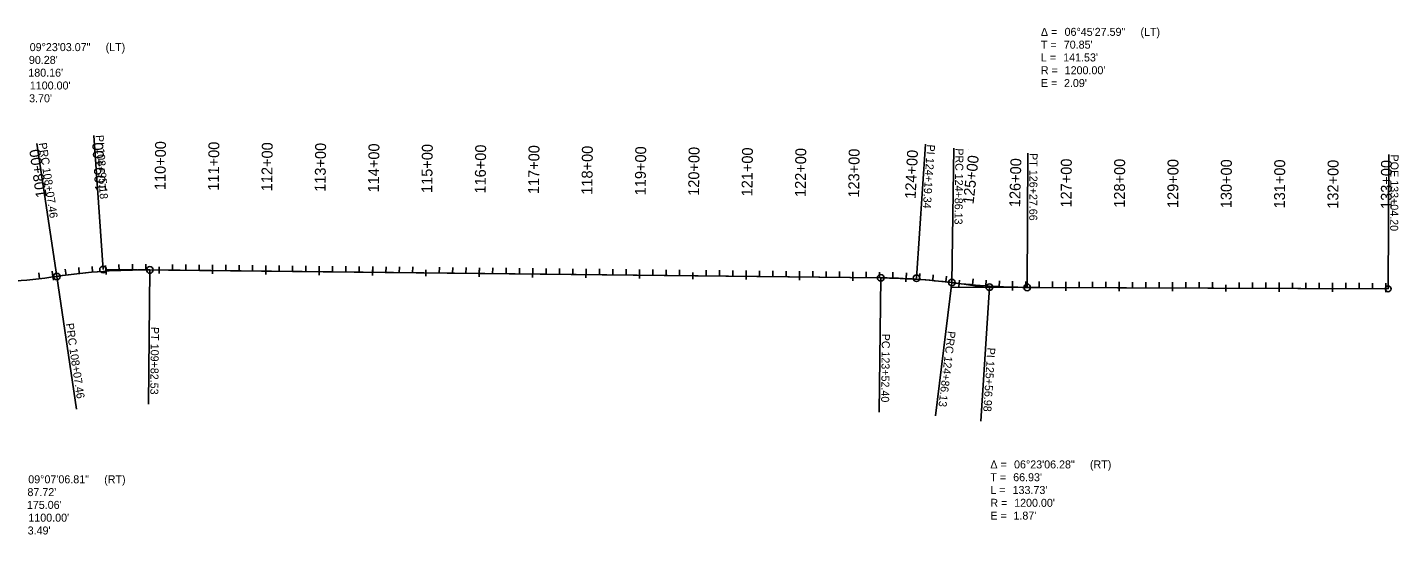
# Model space of a CAD drawing. Extents: x 20504372 to 20508399, y 7970077 to 7971028.
# Drawn here: x 20505829 to 20508399, y 7970077 to 7971028 of the extents above; entities that cross this region are included whole.
import ezdxf

# ---------------------------------------------------------------- set-up
doc = ezdxf.new("R2010")
doc.units = 0
for name, color, linetype in [('SurAlignment', 7, 'Continuous'), ('SurMiscNotes', 7, 'Continuous'), ('TextAlignment', 7, 'Continuous'), ('TextAlignmentSml', 7, 'Continuous')]:
    doc.layers.add(name, color=color, linetype=linetype)

msp = doc.modelspace()

# ---------------------------------------------------------------- linework, layer by layer
at = {"layer": 'SurAlignment'}
for p, q in [((20505977.2, 7970574.1), (20507428.1, 7970558.5)), ((20506058.3, 7970573.3), (20507428.1, 7970558.5)), ((20506058.3, 7970573.3), (20507428.1, 7970558.5)), ((20506058.3, 7970573.3), (20506058.3, 7970573.3)), ((20506058.3, 7970573.3), (20507428.1, 7970558.5)), ((20507562.2, 7970541.2), (20508379.2, 7970537.7)), ((20507702.7, 7970540.6), (20508379.2, 7970537.7))]:
    msp.add_line(p, q, dxfattribs=at)
for centre, radius, start, end in [((20506046.5, 7969473.3), 1100, 89.3818, 98.534), ((20506046.5, 7969473.3), 1100, 89.3818, 98.5003), ((20506046.5, 7969473.3), 1100, 89.3818, 98.5003), ((20505721.3, 7971649.2), 1100, 269.1162, 278.5003), ((20505721.3, 7971649.2), 1100, 269.1162, 278.5003), ((20507415.2, 7969358.5), 1200, 80.1492, 89.3818), ((20507415.2, 7969358.5), 1200, 82.9967, 89.3818), ((20507415.2, 7969358.5), 1200, 82.9967, 89.3818), ((20507707.8, 7971740.6), 1200, 262.9967, 269.7544), ((20507707.8, 7971740.6), 1200, 262.9967, 269.7544)]:
    msp.add_arc(centre, radius, start, end, dxfattribs=at)
at = {"layer": 'SurMiscNotes'}
for p, q in [((20505876.5, 7970560.2), (20505874.9, 7970571)), ((20505975.9, 7970571), (20505975.2, 7970581.9)), ((20506075.9, 7970579.2), (20506075.7, 7970566.9)), ((20506175.8, 7970572), (20506175.9, 7970582.9)), ((20506275.8, 7970570.9), (20506275.9, 7970581.8)), ((20506375.8, 7970569.8), (20506375.9, 7970580.7)), ((20506475.8, 7970568.7), (20506475.9, 7970579.7)), ((20506575.8, 7970573.8), (20506575.7, 7970561.6)), ((20506675.8, 7970566.6), (20506675.9, 7970577.5)), ((20506775.8, 7970565.5), (20506775.9, 7970576.4)), ((20506875.8, 7970564.4), (20506875.9, 7970575.4)), ((20506975.8, 7970563.4), (20506975.9, 7970574.3)), ((20507075.8, 7970568.4), (20507075.7, 7970556.2)), ((20507175.7, 7970561.2), (20507175.9, 7970572.1)), ((20507275.7, 7970560.1), (20507275.9, 7970571)), ((20507375.7, 7970559), (20507375.9, 7970570)), ((20507475.7, 7970557), (20507476.3, 7970567.9)), ((20507576, 7970554.1), (20507574.6, 7970541.9)), ((20507675, 7970541.1), (20507675.3, 7970552)), ((20507775, 7970540.3), (20507775.1, 7970551.3)), ((20507875, 7970539.9), (20507875, 7970550.8)), ((20507975, 7970539.5), (20507975, 7970550.4)), ((20508075, 7970545.2), (20508075, 7970532.9)), ((20508175, 7970538.6), (20508175, 7970549.5)), ((20508275, 7970538.2), (20508275, 7970549.1)), ((20508375, 7970537.8), (20508375, 7970548.7))]:
    msp.add_line(p, q, dxfattribs=at)
at = {"layer": 'TextAlignment'}
for p, q in [((20505970.6, 7970574.2), (20505953.3, 7970825.6)), ((20505953.3, 7970825.6), (20505953.3, 7970825.6)), ((20505883.9, 7970561.2), (20505846.6, 7970810.5)), ((20505846.6, 7970810.5), (20505846.6, 7970810.5)), ((20507495.1, 7970557.8), (20507511.8, 7970809.2)), ((20507511.8, 7970809.2), (20507511.8, 7970809.2)), ((20507561.5, 7970549.6), (20507565, 7970801.6)), ((20507592.2, 7970799.7), (20507592.2, 7970799.7)), ((20507702.7, 7970540.6), (20507703.7, 7970792.6)), ((20507703.7, 7970792.6), (20507703.7, 7970792.6)), ((20508379.2, 7970537.7), (20508380.3, 7970789.7)), ((20508380.3, 7970789.7), (20508380.3, 7970789.7)), ((20506058.3, 7970573.3), (20506055.6, 7970321.3)), ((20505883.9, 7970561.2), (20505921.1, 7970312)), ((20507428.1, 7970558.5), (20507425.4, 7970306.5)), ((20507561.5, 7970549.6), (20507530.8, 7970299.5)), ((20507631.8, 7970541), (20507615.9, 7970289.5)), ((20505921.1, 7970312), (20505921.1, 7970312)), ((20506055.6, 7970321.3), (20506055.6, 7970321.3)), ((20507425.4, 7970306.5), (20507425.4, 7970306.5)), ((20507530.8, 7970299.5), (20507530.8, 7970299.5)), ((20507615.9, 7970289.5), (20507615.9, 7970289.5))]:
    msp.add_line(p, q, dxfattribs=at)
for centre, radius in [((20505883.9, 7970561.2), 6.24), ((20505883.9, 7970561.2), 6.24), ((20505970.6, 7970574.2), 6.24), ((20506058.3, 7970573.3), 6.24), ((20507428.1, 7970558.5), 6.24), ((20507495.1, 7970557.8), 6.24), ((20507561.5, 7970549.6), 6.24), ((20507561.5, 7970549.6), 6.24), ((20507631.8, 7970541), 6.24), ((20507702.7, 7970540.6), 6.24), ((20508379.2, 7970537.7), 5.34)]:
    msp.add_circle(centre, radius, dxfattribs=at)
at = {"layer": 'TextAlignmentSml'}
for p, q in [((20505851.7, 7970556.9), (20505850.4, 7970567.8)), ((20505875.6, 7970566.2), (20505877.4, 7970554.1)), ((20505901.2, 7970563.7), (20505899.8, 7970574.5)), ((20505926.1, 7970566.7), (20505924.9, 7970577.6)), ((20505950.9, 7970569.2), (20505950, 7970580)), ((20505975.5, 7970577.2), (20505976.3, 7970564.9)), ((20506000.8, 7970572.4), (20506000.4, 7970583.3)), ((20506025.8, 7970573.1), (20506025.6, 7970584)), ((20506050.8, 7970573.3), (20506050.9, 7970584.2)), ((20506075.9, 7970579.2), (20506075.7, 7970566.9)), ((20506100.8, 7970572.8), (20506100.9, 7970583.7)), ((20506125.8, 7970572.5), (20506125.9, 7970583.4)), ((20506150.8, 7970572.3), (20506150.9, 7970583.2)), ((20506175.9, 7970578.1), (20506175.7, 7970565.9)), ((20506200.8, 7970571.7), (20506200.9, 7970582.6)), ((20506225.8, 7970571.4), (20506225.9, 7970582.4)), ((20506250.8, 7970571.2), (20506250.9, 7970582.1)), ((20506275.9, 7970577), (20506275.7, 7970564.8)), ((20506300.8, 7970570.6), (20506300.9, 7970581.6)), ((20506325.8, 7970570.4), (20506325.9, 7970581.3)), ((20506350.8, 7970570.1), (20506350.9, 7970581)), ((20506375.9, 7970575.9), (20506375.7, 7970563.7)), ((20506400.8, 7970569.6), (20506400.9, 7970580.5)), ((20506425.8, 7970569.3), (20506425.9, 7970580.2)), ((20506450.8, 7970569), (20506450.9, 7970579.9)), ((20506475.9, 7970574.9), (20506475.7, 7970562.6)), ((20506500.8, 7970568.5), (20506500.9, 7970579.4)), ((20506525.8, 7970568.2), (20506525.9, 7970579.1)), ((20506550.8, 7970567.9), (20506550.9, 7970578.9)), ((20506575.8, 7970573.8), (20506575.7, 7970561.6)), ((20506600.8, 7970567.4), (20506600.9, 7970578.3)), ((20506625.8, 7970567.1), (20506625.9, 7970578.1)), ((20506650.8, 7970566.9), (20506650.9, 7970577.8)), ((20506675.8, 7970572.7), (20506675.7, 7970560.5)), ((20506700.8, 7970566.3), (20506700.9, 7970577.2)), ((20506725.8, 7970566.1), (20506725.9, 7970577)), ((20506750.8, 7970565.8), (20506750.9, 7970576.7)), ((20506775.8, 7970571.6), (20506775.7, 7970559.4)), ((20506800.8, 7970565.2), (20506800.9, 7970576.2)), ((20506825.8, 7970565), (20506825.9, 7970575.9)), ((20506850.8, 7970564.7), (20506850.9, 7970575.6)), ((20506875.8, 7970570.6), (20506875.7, 7970558.3)), ((20506900.8, 7970564.2), (20506900.9, 7970575.1)), ((20506925.8, 7970563.9), (20506925.9, 7970574.8)), ((20506950.8, 7970563.6), (20506950.9, 7970574.5)), ((20506975.8, 7970569.5), (20506975.7, 7970557.2)), ((20507000.8, 7970563.1), (20507000.9, 7970574)), ((20507025.8, 7970562.8), (20507025.9, 7970573.7)), ((20507050.8, 7970562.5), (20507050.9, 7970573.5)), ((20507075.8, 7970568.4), (20507075.7, 7970556.2)), ((20507100.8, 7970562), (20507100.9, 7970572.9)), ((20507125.8, 7970561.7), (20507125.9, 7970572.7)), ((20507150.7, 7970561.5), (20507150.9, 7970572.4)), ((20507175.8, 7970567.3), (20507175.7, 7970555.1)), ((20507200.7, 7970560.9), (20507200.9, 7970571.8)), ((20507225.7, 7970560.7), (20507225.9, 7970571.6)), ((20507250.7, 7970560.4), (20507250.9, 7970571.3)), ((20507275.8, 7970566.2), (20507275.7, 7970554)), ((20507300.7, 7970559.8), (20507300.9, 7970570.8)), ((20507325.7, 7970559.6), (20507325.9, 7970570.5)), ((20507350.7, 7970559.3), (20507350.9, 7970570.2)), ((20507375.8, 7970565.2), (20507375.7, 7970552.9)), ((20507400.7, 7970558.8), (20507400.9, 7970569.7)), ((20507425.7, 7970558.5), (20507425.9, 7970569.4)), ((20507450.7, 7970558), (20507451.1, 7970568.9)), ((20507500.7, 7970555.5), (20507501.4, 7970566.4)), ((20507525.6, 7970553.5), (20507526.6, 7970564.3)), ((20507476, 7970563.1), (20507475.4, 7970550.9)), ((20507550.4, 7970550.9), (20507551.7, 7970561.7)), ((20507576, 7970554.1), (20507574.6, 7970541.9)), ((20507600.1, 7970545.5), (20507601.1, 7970556.4)), ((20507625.1, 7970543.5), (20507625.8, 7970554.4)), ((20507650, 7970542), (20507650.6, 7970552.9)), ((20507675.2, 7970547.2), (20507674.8, 7970535)), ((20507700, 7970540.7), (20507700.1, 7970551.6)), ((20507725, 7970540.6), (20507725.1, 7970551.5)), ((20507750, 7970540.4), (20507750.1, 7970551.4)), ((20507775, 7970546.5), (20507775, 7970534.2)), ((20507800, 7970540.2), (20507800.1, 7970551.2)), ((20507825, 7970540.1), (20507825, 7970551)), ((20507850, 7970540), (20507850, 7970550.9)), ((20507875, 7970546), (20507875, 7970533.8)), ((20507900, 7970539.8), (20507900, 7970550.7)), ((20507925, 7970539.7), (20507925, 7970550.6)), ((20507950, 7970539.6), (20507950, 7970550.5)), ((20507975, 7970545.6), (20507975, 7970533.4)), ((20508000, 7970539.4), (20508000, 7970550.3)), ((20508025, 7970539.3), (20508025, 7970550.2)), ((20508050, 7970539.2), (20508050, 7970550.1)), ((20508075, 7970545.2), (20508075, 7970532.9)), ((20508100, 7970538.9), (20508100, 7970549.9)), ((20508125, 7970538.8), (20508125, 7970549.8)), ((20508150, 7970538.7), (20508150, 7970549.7)), ((20508175, 7970544.7), (20508175, 7970532.5)), ((20508200, 7970538.5), (20508200, 7970549.4)), ((20508225, 7970538.4), (20508225, 7970549.3)), ((20508250, 7970538.3), (20508250, 7970549.2)), ((20508275, 7970544.3), (20508275, 7970532.1)), ((20508300, 7970538.1), (20508300, 7970549)), ((20508325, 7970538), (20508325, 7970548.9)), ((20508350, 7970537.9), (20508350, 7970548.8)), ((20508375, 7970543.9), (20508375, 7970531.6))]:
    msp.add_line(p, q, dxfattribs=at)

# ---------------------------------------------------------------- texts
at = {"layer": 'SurMiscNotes'}
for s, rotation, p in [('110+00', 89.3818, (20506087.6, 7970722.9)), ('115+00', 89.3818, (20506587.6, 7970717.6)), ('120+00', 89.3818, (20507087.6, 7970712.2)), ('125+00', 83.6589, (20507602, 7970695.9)), ('130+00', 89.7544, (20508085.8, 7970689))]:
    msp.add_text(s, height=20.4, rotation=rotation, dxfattribs=at).set_placement(p)
at = {"layer": 'TextAlignment'}
for s, p in [('Δ = ', (20507728.3, 7971012.3)), ('06°45\'27.59"', (20507772.7, 7971012.3)), (' (LT)', (20507909.4, 7971012.3)), ('T = ', (20507728.3, 7970988.3)), ("70.85'", (20507771.2, 7970988.3)), ('09°23\'03.07"', (20505833.1, 7970983.7)), (' (LT)', (20505969.8, 7970983.7)), ('L = ', (20507728.3, 7970964.3)), ("141.53'", (20507770.1, 7970964.3)), ("180.16'", (20505830.5, 7970935.7)), ("90.28'", (20505831.6, 7970959.7)), ('R = ', (20507728.3, 7970940.3)), ("1200.00'", (20507772.9, 7970940.3)), ("1100.00'", (20505833.3, 7970911.7)), ('E = ', (20507728.3, 7970916.3)), ("2.09'", (20507771.6, 7970916.3)), ("3.70'", (20505832, 7970887.7)), ('Δ = ', (20507633.6, 7970201.1)), ('06°23\'06.28"', (20507678, 7970201.1)), (' (RT)', (20507814.7, 7970201.1)), ('09°07\'06.81"', (20505830.4, 7970173.2)), (' (RT)', (20505967.1, 7970173.2)), ('T = ', (20507633.6, 7970177.1)), ("66.93'", (20507676.4, 7970177.1)), ("87.72'", (20505828.9, 7970149.2)), ('L = ', (20507633.6, 7970153.1)), ("133.73'", (20507675.3, 7970153.1)), ("175.06'", (20505827.8, 7970125.2)), ('R = ', (20507633.6, 7970129.1)), ("1200.00'", (20507678.2, 7970129.1)), ("1100.00'", (20505830.6, 7970101.2)), ('E = ', (20507633.6, 7970105.1)), ("1.87'", (20507676.9, 7970105.1)), ("3.49'", (20505829.3, 7970077.2))]:
    msp.add_text(s, height=15, dxfattribs=at).set_placement(p)
for s, rotation, p in [('PI ', 273.9411, (20505956.6, 7970825.8)), ('PRC', 278.5003, (20505849.9, 7970811)), ('108+95.18', 273.9411, (20505958.3, 7970800.9)), ('PI ', 266.1892, (20507515.1, 7970809)), ('PRC', 269.2115, (20507568.3, 7970801.5)), ('124+19.34', 266.1892, (20507513.4, 7970784)), ('PT', 269.7544, (20507707, 7970792.6)), ('POE ', 269.7544, (20508383.6, 7970789.7)), ('108+07.46', 278.5003, (20505856.9, 7970763.9)), ('124+86.13', 269.2115, (20507567.6, 7970753.9)), ('126+27.66', 269.7544, (20507706.9, 7970761.1)), ('133+04.20', 269.7544, (20508383.4, 7970741.6)), ('PRC', 278.5003, (20505900.5, 7970472.5)), ('PT', 269.3818, (20506060.5, 7970466.5)), ('PC', 269.3818, (20507430.3, 7970453.8)), ('PRC', 262.9967, (20507553.7, 7970459.3)), ('108+07.46', 278.5003, (20505907.5, 7970425.4)), ('109+82.53', 269.3818, (20506060.1, 7970435)), ('123+52.40', 269.3818, (20507429.9, 7970420.5)), ('124+86.13', 262.9967, (20507547.9, 7970412)), ('PI ', 266.3755, (20507628, 7970428)), ('125+56.98', 266.3755, (20507626.4, 7970403.1))]:
    msp.add_text(s, height=15, rotation=rotation, dxfattribs=at).set_placement(p)
at = {"layer": 'TextAlignmentSml'}
for s, rotation, p in [('108+00', 98.1116, (20505865.4, 7970710.1)), ('109+00', 93.6804, (20505976.4, 7970721.4)), ('110+00', 89.3818, (20506087.6, 7970722.9)), ('111+00', 89.3818, (20506187.6, 7970721.9)), ('112+00', 89.3818, (20506287.6, 7970720.8)), ('113+00', 89.3818, (20506387.6, 7970719.7)), ('114+00', 89.3818, (20506487.6, 7970718.6)), ('115+00', 89.3818, (20506587.6, 7970717.6)), ('116+00', 89.3818, (20506687.6, 7970716.5)), ('117+00', 89.3818, (20506787.6, 7970715.4)), ('118+00', 89.3818, (20506887.6, 7970714.3)), ('119+00', 89.3818, (20506987.6, 7970713.2)), ('120+00', 89.3818, (20507087.6, 7970712.2)), ('121+00', 89.3818, (20507187.6, 7970711.1)), ('122+00', 89.3818, (20507287.6, 7970710)), ('123+00', 89.3818, (20507387.6, 7970708.9)), ('124+00', 87.1091, (20507493.5, 7970706.3)), ('125+00', 83.6589, (20507602, 7970695.9)), ('126+00', 88.4336, (20507689.3, 7970690.8)), ('127+00', 89.7544, (20507785.8, 7970690.3)), ('128+00', 89.7544, (20507885.8, 7970689.9)), ('129+00', 89.7544, (20507985.8, 7970689.4)), ('130+00', 89.7544, (20508085.8, 7970689)), ('131+00', 89.7544, (20508185.8, 7970688.6)), ('132+00', 89.7544, (20508285.8, 7970688.1)), ('133+00', 89.7544, (20508385.8, 7970687.7))]:
    msp.add_text(s, height=20.4, rotation=rotation, dxfattribs=at).set_placement(p)

doc.saveas('drawing.dxf')
